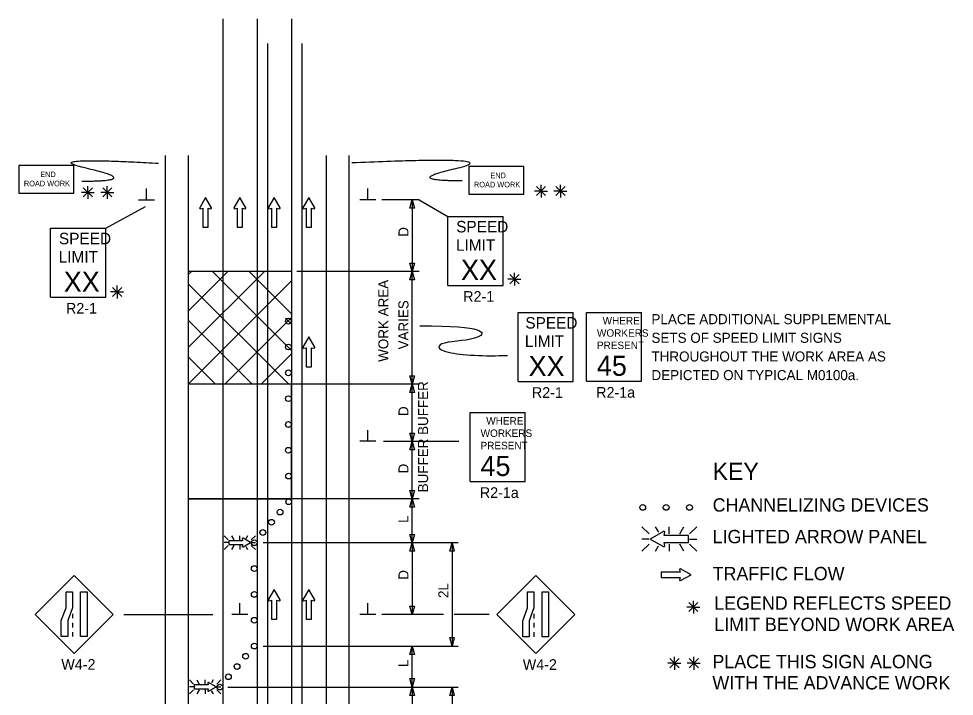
# Model space of a CAD drawing. Extents: x 16725 to 18475, y 5932 to 7023.
# Drawn here: x 16757 to 17408, y 6551 to 7023 of the extents above; entities that cross this region are included whole.
import ezdxf

# ---------------------------------------------------------------- set-up
doc = ezdxf.new("R2010")
doc.units = 0
for name, color, linetype in [('ALI_LEGAL_EX', 7, 'Continuous'), ('MT_SCRATCH_LEVEL_A', 7, 'Continuous'), ('MT_SCRATCH_LEVEL_E', 7, 'Continuous'), ('PAVT_EDGE_EX', 7, 'Continuous'), ('TRAFFIC_SIGNS_PR', 7, 'Continuous'), ('TYPICAL_TEXT_DIMEN_EX', 7, 'Continuous'), ('TYPICAL_TEXT_DIMEN_PR', 7, 'Continuous')]:
    doc.layers.add(name, color=color, linetype=linetype)

msp = doc.modelspace()

# ---------------------------------------------------------------- linework, layer by layer
at = {"layer": 'ALI_LEGAL_EX'}
for p, q in [((16898.69, 7022.86), (16898.69, 6323.13)), ((16922.69, 7022.86), (16922.69, 6323.13)), ((16946.69, 7022.86), (16946.69, 6323.13)), ((16929.88, 7005.57), (16929.88, 6176.39)), ((16953.88, 7005.57), (16953.88, 6176.39)), ((16953.88, 7005.57), (16953.88, 6176.39))]:
    msp.add_line(p, q, dxfattribs=at)
for points in [[(16898.69, 6882.86), (16898.69, 6857.86)], [(16922.69, 6882.86), (16922.69, 6857.86)], [(16946.69, 6882.86), (16946.69, 6857.86)], [(16898.69, 6782.86), (16898.69, 6757.86)], [(16922.69, 6782.86), (16922.69, 6757.86)], [(16946.69, 6782.86), (16946.69, 6757.86)], [(16898.69, 6682.86), (16898.69, 6657.86)], [(16922.69, 6682.86), (16922.69, 6657.86)], [(16898.69, 6582.86), (16898.69, 6557.86)], [(16946.69, 6582.86), (16946.69, 6557.86)]]:
    msp.add_lwpolyline(points, dxfattribs=at)
at = {"layer": 'MT_SCRATCH_LEVEL_A'}
for p, q in [((16946.69, 6846.64), (16874.69, 6846.64)), ((16874.69, 6846.64), (16874.69, 6738.67)), ((16946.69, 6846.64), (16874.69, 6846.64)), ((16874.69, 6846.64), (16874.69, 6768.1)), ((16874.69, 6844.47), (16876.86, 6846.64)), ((16874.69, 6819.01), (16902.32, 6846.64)), ((16874.69, 6793.56), (16927.77, 6846.64)), ((16946.69, 6791.56), (16891.62, 6846.64)), ((16946.69, 6817.01), (16917.07, 6846.64)), ((16874.69, 6768.1), (16946.69, 6840.1)), ((16944.7, 6768.1), (16874.69, 6838.1)), ((16919.24, 6768.1), (16874.69, 6812.65)), ((16900.15, 6768.1), (16946.69, 6814.64)), ((16946.6, 6809.85), (16942.43, 6814.01)), ((16893.79, 6768.1), (16874.69, 6787.19)), ((16925.61, 6768.1), (16946.69, 6789.19)), ((16946.69, 6768.1), (16874.69, 6768.1))]:
    msp.add_line(p, q, dxfattribs=at)
at = {"layer": 'MT_SCRATCH_LEVEL_E'}
for p, q in [((16886.79, 6898.33), (16882.68, 6891.09)), ((16890.94, 6891.09), (16886.79, 6898.33)), ((16910.69, 6898.33), (16906.58, 6891.09)), ((16914.84, 6891.09), (16910.69, 6898.33)), ((16934.6, 6898.33), (16930.49, 6891.09)), ((16938.74, 6891.09), (16934.6, 6898.33)), ((16958.65, 6898.33), (16954.54, 6891.09)), ((16962.8, 6891.09), (16958.65, 6898.33)), ((16883.16, 6890.41), (16884.94, 6890.72)), ((16884.94, 6890.72), (16884.94, 6877.46)), ((16888.68, 6877.46), (16888.68, 6890.72)), ((16888.68, 6890.72), (16890.46, 6890.41)), ((16907.06, 6890.41), (16908.84, 6890.72)), ((16908.84, 6890.72), (16908.84, 6877.46)), ((16912.58, 6877.46), (16912.58, 6890.72)), ((16912.58, 6890.72), (16914.36, 6890.41)), ((16930.97, 6890.41), (16932.74, 6890.72)), ((16932.74, 6890.72), (16932.74, 6877.46)), ((16936.49, 6877.46), (16936.49, 6890.72)), ((16936.49, 6890.72), (16938.26, 6890.41)), ((16955.02, 6890.41), (16956.8, 6890.72)), ((16956.8, 6890.72), (16956.8, 6877.46)), ((16960.54, 6877.46), (16960.54, 6890.72)), ((16960.54, 6890.72), (16962.32, 6890.41)), ((16884.94, 6877.46), (16888.68, 6877.46)), ((16908.84, 6877.46), (16912.58, 6877.46)), ((16932.74, 6877.46), (16936.49, 6877.46)), ((16956.8, 6877.46), (16960.54, 6877.46)), ((16958.65, 6801.06), (16954.54, 6793.82)), ((16962.8, 6793.82), (16958.65, 6801.06)), ((16955.02, 6793.13), (16956.8, 6793.45)), ((16956.8, 6793.45), (16956.8, 6780.19)), ((16960.54, 6780.19), (16960.54, 6793.45)), ((16960.54, 6793.45), (16962.32, 6793.13)), ((16956.8, 6780.19), (16960.54, 6780.19)), ((17217.36, 6637.12), (17204.11, 6637.12)), ((17204.11, 6637.12), (17204.11, 6633.38)), ((17217.05, 6638.9), (17217.36, 6637.12)), ((17224.97, 6635.27), (17217.73, 6639.38)), ((17204.11, 6633.38), (17217.36, 6633.38)), ((17217.36, 6633.38), (17217.05, 6631.6)), ((17217.73, 6631.12), (17224.97, 6635.27)), ((16934.6, 6625.06), (16930.49, 6617.82)), ((16938.74, 6617.82), (16934.6, 6625.06)), ((16958.65, 6625.06), (16954.54, 6617.82)), ((16962.8, 6617.82), (16958.65, 6625.06)), ((16930.97, 6617.14), (16932.74, 6617.45)), ((16932.74, 6617.45), (16932.74, 6604.19)), ((16936.49, 6604.19), (16936.49, 6617.45)), ((16936.49, 6617.45), (16938.26, 6617.14)), ((16955.02, 6617.14), (16956.8, 6617.45)), ((16956.8, 6617.45), (16956.8, 6604.19)), ((16960.54, 6604.19), (16960.54, 6617.45)), ((16960.54, 6617.45), (16962.32, 6617.14)), ((16932.74, 6604.19), (16936.49, 6604.19)), ((16956.8, 6604.19), (16960.54, 6604.19))]:
    msp.add_line(p, q, dxfattribs=at)
for centre, start, end in [((16883.09, 6890.87), 150.42484, 279.96381), ((16890.53, 6890.87), 260.03619, 29.77312), ((16906.99, 6890.87), 150.42484, 279.96381), ((16914.43, 6890.87), 260.03619, 29.77312), ((16930.89, 6890.87), 150.42484, 279.96381), ((16938.33, 6890.87), 260.03619, 29.77312), ((16954.95, 6890.87), 150.42484, 279.96381), ((16962.39, 6890.87), 260.03619, 29.77312), ((16954.95, 6793.59), 150.42484, 279.96381), ((16962.39, 6793.59), 260.03619, 29.77312), ((17217.51, 6638.97), 60.42484, 189.96381), ((17217.51, 6631.53), 170.03619, 299.77312), ((16930.89, 6617.59), 150.42484, 279.96381), ((16938.33, 6617.6), 260.03619, 29.77312), ((16954.95, 6617.59), 150.42484, 279.96381), ((16962.39, 6617.6), 260.03619, 29.77312)]:
    msp.add_arc(centre, 0.463, start, end, dxfattribs=at)
at = {"layer": 'PAVT_EDGE_EX'}
for p, q in [((16858.69, 6927.61), (16858.69, 6215.97)), ((16874.69, 6927.61), (16874.69, 6215.97)), ((16970.69, 6927.61), (16970.69, 6215.97)), ((16986.69, 6927.61), (16986.69, 6215.97))]:
    msp.add_line(p, q, dxfattribs=at)
msp.add_lwpolyline([(16946.69, 6768.1), (16874.69, 6768.1), (16874.69, 6688.1), (16946.69, 6688.1)], close=True, dxfattribs=at)
at = {"layer": 'TRAFFIC_SIGNS_PR'}
for p, q in [((17055.59, 6885.03), (17094.03, 6885.03)), ((17055.59, 6836.97), (17055.59, 6885.03)), ((17094.03, 6836.97), (17094.03, 6885.03)), ((16778.85, 6876.77), (16817.3, 6876.77)), ((16778.85, 6828.7), (16778.85, 6876.77)), ((16817.3, 6828.7), (16817.3, 6876.77)), ((17055.59, 6836.97), (17094.03, 6836.97)), ((16778.85, 6828.7), (16817.3, 6828.7)), ((17104.54, 6818), (17142.94, 6818)), ((17104.54, 6770), (17104.54, 6818)), ((17142.94, 6770), (17142.94, 6818)), ((17152.09, 6818.09), (17190.49, 6818.09)), ((17152.09, 6770.09), (17152.09, 6818.09)), ((17190.49, 6770.09), (17190.49, 6818.09)), ((17104.54, 6770), (17142.94, 6770)), ((17152.09, 6770.09), (17190.49, 6770.09)), ((17071.02, 6748.23), (17109.42, 6748.23)), ((17071.02, 6700.23), (17071.02, 6748.23)), ((17109.42, 6700.23), (17109.42, 6748.23)), ((17071.02, 6700.23), (17109.42, 6700.23)), ((17190.78, 6668.65), (17195.72, 6663.72)), ((17202.55, 6664.83), (17200.34, 6668.65)), ((17209.87, 6663.72), (17209.87, 6668.65)), ((17217.1, 6663.72), (17219.95, 6668.65)), ((17224.02, 6663.72), (17228.95, 6668.65)), ((16902.47, 6659.64), (16899.65, 6662.46)), ((16904.77, 6662.46), (16906.39, 6659.64)), ((16910.55, 6659.64), (16910.55, 6662.46)), ((16916.02, 6662.46), (16914.82, 6660.36)), ((16921.46, 6662.46), (16918.64, 6659.64)), ((16902.47, 6657.61), (16899.65, 6657.61)), ((16902.47, 6655.57), (16899.65, 6652.75)), ((16906.42, 6655.57), (16904.79, 6652.75)), ((16910.55, 6655.57), (16910.55, 6652.75)), ((16918.64, 6657.61), (16921.46, 6657.61)), ((16921.46, 6652.76), (16918.64, 6655.57)), ((17195.72, 6660.16), (17190.78, 6660.16)), ((17190.78, 6651.67), (17195.72, 6656.61)), ((17200.3, 6651.67), (17202.41, 6655.33)), ((17209.87, 6656.61), (17209.87, 6651.67)), ((17220, 6651.67), (17217.15, 6656.61)), ((17224.02, 6660.16), (17228.95, 6660.16)), ((17224.02, 6656.61), (17228.95, 6651.67)), ((16914.74, 6654.94), (16916, 6652.75)), ((16795.32, 6634.75), (16768.17, 6607.6)), ((16822.47, 6607.6), (16795.32, 6634.75)), ((17116.81, 6634.7), (17089.66, 6607.55)), ((17143.96, 6607.55), (17116.81, 6634.7)), ((16768.17, 6607.6), (16795.32, 6580.45)), ((16794.07, 6608.09), (16794.07, 6604.89)), ((16795.32, 6580.45), (16822.47, 6607.6)), ((17089.66, 6607.55), (17116.81, 6580.39)), ((17115.56, 6608.04), (17115.56, 6604.84)), ((17116.81, 6580.39), (17143.96, 6607.55)), ((16794.07, 6601.69), (16794.07, 6598.49)), ((17115.56, 6601.64), (17115.56, 6598.44)), ((16794.07, 6595.29), (16794.07, 6592.09)), ((17115.56, 6595.24), (17115.56, 6592.04)), ((16878.47, 6559.07), (16875.65, 6561.9)), ((16880.77, 6561.9), (16882.39, 6559.07)), ((16886.55, 6559.07), (16886.55, 6561.9)), ((16892.02, 6561.9), (16890.82, 6559.8)), ((16897.46, 6561.89), (16894.64, 6559.07)), ((16878.47, 6557.04), (16875.65, 6557.04)), ((16878.47, 6555.01), (16875.65, 6552.19)), ((16882.42, 6555.01), (16880.79, 6552.19)), ((16886.55, 6555.01), (16886.55, 6552.19)), ((16890.74, 6554.38), (16892, 6552.19)), ((16894.64, 6557.04), (16897.46, 6557.04)), ((16897.46, 6552.19), (16894.64, 6555.01))]:
    msp.add_line(p, q, dxfattribs=at)
for points in [[(16756.59, 6901.32), (16794.99, 6901.32), (16794.99, 6920.52), (16756.59, 6920.52)], [(17070.18, 6900.57), (17108.58, 6900.57), (17108.58, 6919.77), (17070.18, 6919.77)], [(16794.07, 6623.34), (16794.07, 6612.15), (16790.73, 6603.27), (16790.73, 6592.09), (16786.24, 6592.09), (16786.24, 6603.27), (16789.58, 6612.15), (16789.58, 6623.34)], [(16804.21, 6623.34), (16804.21, 6592.09), (16799.72, 6592.09), (16799.72, 6623.34)], [(17115.56, 6623.28), (17115.56, 6612.1), (17112.22, 6603.22), (17112.22, 6592.04), (17107.73, 6592.04), (17107.73, 6603.22), (17111.07, 6612.1), (17111.07, 6623.28)], [(17125.7, 6623.28), (17125.7, 6592.04), (17121.21, 6592.04), (17121.21, 6623.28)]]:
    msp.add_lwpolyline(points, close=True, dxfattribs=at)
for points in [[(17205.79, 6665.44), (17196.5, 6660.16), (17205.8, 6654.84)], [(17206.67, 6655.47), (17206.27, 6657.74), (17223.28, 6657.74), (17223.28, 6662.54), (17206.27, 6662.54), (17206.67, 6664.82)], [(16912.38, 6660.29), (16912.61, 6658.99), (16902.89, 6658.99), (16902.89, 6656.25), (16912.61, 6656.25), (16912.38, 6654.94)], [(16912.88, 6654.59), (16918.19, 6657.61), (16912.88, 6660.65)], [(16888.38, 6559.73), (16888.61, 6558.43), (16878.89, 6558.43), (16878.89, 6555.69), (16888.61, 6555.69), (16888.38, 6554.38)], [(16888.88, 6554.03), (16894.19, 6557.04), (16888.88, 6560.08)]]:
    msp.add_lwpolyline(points, dxfattribs=at)
for centre in [(16944.5, 6812), (16944.5, 6794), (16944.5, 6776), (16944.5, 6758), (16944.5, 6740), (16944.5, 6722), (16944.59, 6704.05), (16944.69, 6686.1), (17191.35, 6682.19), (17207.65, 6682.19), (17223.95, 6682.19), (16938.69, 6678.96), (16932.69, 6671.82), (16926.69, 6664.68), (16920.69, 6657.54), (16920.69, 6639.54), (16920.69, 6621.54), (16920.69, 6603.54), (16920.69, 6585.54), (16914.69, 6578.39), (16908.69, 6571.25), (16902.69, 6564.11), (16896.69, 6556.97)]:
    msp.add_circle(centre, 2, dxfattribs=at)
for centre, radius, start, end in [((17206.08, 6664.92), 0.598, 350.73078, 118.89165), ((16912.72, 6660.35), 0.341, 61.48329, 189.95933), ((17206.08, 6655.37), 0.597, 241.48329, 9.95933), ((16912.72, 6654.89), 0.341, 170.73078, 298.89165), ((16888.72, 6559.78), 0.341, 61.48329, 189.95933), ((16888.72, 6554.33), 0.341, 170.73078, 298.89165)]:
    msp.add_arc(centre, radius, start, end, dxfattribs=at)
for points in [[(16800.52, 6909.62), (16843.03, 6909.62), (16766.51, 6927.04), (16854.05, 6922.1)], [(17065.47, 6909.8), (17022.96, 6909.8), (17099.47, 6927.21), (16988.69, 6922.27)]]:
    msp.add_open_spline(points, degree=2, dxfattribs=at)
at = {"layer": 'TYPICAL_TEXT_DIMEN_PR'}
for p, q in [((16801.58, 6904.96), (16807.96, 6898.59)), ((16807.96, 6904.96), (16801.58, 6898.59)), ((16804.77, 6901.78), (16804.77, 6906.23)), ((16815.09, 6904.96), (16821.46, 6898.59)), ((16821.46, 6904.96), (16815.09, 6898.59)), ((16818.28, 6901.78), (16818.28, 6906.23)), ((16845.57, 6896.64), (16845.57, 6904.42)), ((16999.82, 6896.64), (16999.82, 6904.42)), ((17120.52, 6902.69), (17115.99, 6902.69)), ((17117.33, 6905.88), (17123.71, 6899.5)), ((17123.71, 6905.88), (17117.33, 6899.5)), ((17120.52, 6902.69), (17120.52, 6907.15)), ((17120.52, 6902.69), (17123.71, 6902.69)), ((17120.52, 6902.69), (17125, 6902.69)), ((17120.52, 6902.69), (17120.52, 6898.19)), ((17134.03, 6902.69), (17129.49, 6902.69)), ((17130.84, 6905.88), (17137.21, 6899.5)), ((17137.21, 6905.88), (17130.84, 6899.5)), ((17134.03, 6902.69), (17134.03, 6907.15)), ((17134.03, 6902.69), (17137.21, 6902.69)), ((17134.03, 6902.69), (17138.5, 6902.69)), ((17134.03, 6902.69), (17134.03, 6898.19)), ((16804.77, 6901.78), (16800.24, 6901.78)), ((16804.77, 6901.78), (16807.96, 6901.78)), ((16804.77, 6901.78), (16809.25, 6901.78)), ((16804.77, 6901.78), (16804.77, 6897.28)), ((16818.28, 6901.78), (16813.74, 6901.78)), ((16818.28, 6901.78), (16821.46, 6901.78)), ((16818.28, 6901.78), (16822.75, 6901.78)), ((16818.28, 6901.78), (16818.28, 6897.28)), ((16839.94, 6896.64), (16851.19, 6896.64)), ((17005.44, 6896.64), (16994.19, 6896.64)), ((17035.69, 6896.64), (17009.69, 6896.64)), ((17029.12, 6890.77), (17030.69, 6896.64)), ((17030.69, 6896.64), (17030.69, 6846.64)), ((17030.69, 6896.64), (17032.26, 6890.77)), ((17035.69, 6896.64), (17055.59, 6885.03)), ((16817.25, 6876.77), (16844.96, 6892.05)), ((17030.69, 6890.77), (17029.12, 6890.77)), ((17032.26, 6890.77), (17030.69, 6890.77)), ((17030.69, 6846.64), (17029.12, 6852.5)), ((17029.12, 6852.5), (17030.69, 6852.5)), ((17030.69, 6852.5), (17032.26, 6852.5)), ((17032.26, 6852.5), (17030.69, 6846.64)), ((17035.69, 6846.64), (16950.31, 6846.64)), ((17029.12, 6840.77), (17030.69, 6846.64)), ((17030.69, 6768.1), (17030.69, 6846.64)), ((17030.69, 6846.64), (17032.26, 6840.77)), ((17098.79, 6844.52), (17105.16, 6838.14)), ((17105.16, 6844.52), (17098.79, 6838.14)), ((17101.97, 6841.33), (17101.97, 6845.79)), ((17030.69, 6840.77), (17029.12, 6840.77)), ((17032.26, 6840.77), (17030.69, 6840.77)), ((17101.97, 6841.33), (17097.44, 6841.33)), ((17101.97, 6841.33), (17105.16, 6841.33)), ((17101.97, 6841.33), (17106.45, 6841.33)), ((17101.97, 6841.33), (17101.97, 6836.83)), ((16825.14, 6832.39), (16820.6, 6832.39)), ((16821.95, 6835.57), (16828.32, 6829.2)), ((16828.32, 6835.57), (16821.95, 6829.2)), ((16825.14, 6832.39), (16825.14, 6836.84)), ((16825.14, 6832.39), (16828.32, 6832.39)), ((16825.14, 6832.39), (16829.61, 6832.39)), ((16825.14, 6832.39), (16825.14, 6827.89)), ((17030.69, 6768.1), (17029.12, 6773.96)), ((17029.12, 6773.96), (17030.69, 6773.96)), ((17030.69, 6773.96), (17032.26, 6773.96)), ((17032.26, 6773.96), (17030.69, 6768.1)), ((17035.69, 6768.1), (16946.69, 6768.1)), ((17029.12, 6762.24), (17030.69, 6768.1)), ((17030.69, 6728.1), (17030.69, 6768.1)), ((17030.69, 6768.1), (17032.26, 6762.24)), ((17030.69, 6762.24), (17029.12, 6762.24)), ((17032.26, 6762.24), (17030.69, 6762.24)), ((16999.82, 6728.36), (16999.82, 6736.14)), ((17030.69, 6728.1), (17029.12, 6733.96)), ((17029.12, 6733.96), (17030.69, 6733.96)), ((17030.69, 6733.96), (17032.26, 6733.96)), ((17032.26, 6733.96), (17030.69, 6728.1)), ((17005.44, 6728.36), (16994.19, 6728.36)), ((17063.31, 6728.1), (17010.84, 6728.1)), ((17029.12, 6722.24), (17030.69, 6728.1)), ((17030.69, 6688.1), (17030.69, 6728.1)), ((17030.69, 6728.1), (17032.26, 6722.24)), ((17030.69, 6722.24), (17029.12, 6722.24)), ((17032.26, 6722.24), (17030.69, 6722.24)), ((17035.69, 6688.1), (16874.69, 6688.1)), ((17030.69, 6688.1), (17029.12, 6693.96)), ((17029.12, 6693.96), (17030.69, 6693.96)), ((17029.12, 6682.24), (17030.69, 6688.1)), ((17030.69, 6693.96), (17032.26, 6693.96)), ((17032.26, 6693.96), (17030.69, 6688.1)), ((17030.69, 6657.53), (17030.69, 6688.1)), ((17030.69, 6688.1), (17032.26, 6682.24)), ((17030.69, 6682.24), (17029.12, 6682.24)), ((17032.26, 6682.24), (17030.69, 6682.24)), ((17030.69, 6657.53), (17029.12, 6663.4)), ((17029.12, 6663.4), (17030.69, 6663.4)), ((17030.69, 6663.4), (17032.26, 6663.4)), ((17032.26, 6663.4), (17030.69, 6657.53)), ((17062.74, 6657.53), (16926.92, 6657.53)), ((17029.12, 6651.67), (17030.69, 6657.53)), ((17030.69, 6657.53), (17030.69, 6607.53)), ((17030.69, 6657.53), (17032.26, 6651.67)), ((17056.93, 6651.67), (17058.5, 6657.53)), ((17058.5, 6657.53), (17060.07, 6651.67)), ((17058.5, 6657.53), (17058.5, 6585.53)), ((17030.69, 6651.67), (17029.12, 6651.67)), ((17032.26, 6651.67), (17030.69, 6651.67)), ((17058.5, 6651.67), (17056.93, 6651.67)), ((17060.07, 6651.67), (17058.5, 6651.67)), ((17229.84, 6615.89), (17223.46, 6609.51)), ((17223.47, 6615.89), (17229.84, 6609.51)), ((17226.65, 6612.7), (17226.65, 6617.16)), ((16910.64, 6607.53), (16910.64, 6615.32)), ((16999.82, 6607.53), (16999.82, 6615.32)), ((17030.69, 6607.53), (17029.12, 6613.4)), ((17029.12, 6613.4), (17030.69, 6613.4)), ((17030.69, 6613.4), (17032.26, 6613.4)), ((17032.26, 6613.4), (17030.69, 6607.53)), ((17226.65, 6612.7), (17222.12, 6612.7)), ((17226.65, 6612.7), (17229.84, 6612.7)), ((17226.65, 6612.7), (17231.13, 6612.7)), ((17226.65, 6612.7), (17226.65, 6608.2)), ((16829.94, 6607.53), (16891.95, 6607.53)), ((16916.26, 6607.53), (16905.01, 6607.53)), ((17005.44, 6607.53), (16994.19, 6607.53)), ((17052.49, 6607.53), (17009.69, 6607.53)), ((17084.27, 6607.53), (17060.06, 6607.53)), ((17058.5, 6585.53), (17056.93, 6591.4)), ((17056.93, 6591.4), (17058.5, 6591.4)), ((17058.5, 6591.4), (17060.07, 6591.4)), ((17060.07, 6591.4), (17058.5, 6585.53)), ((16926.92, 6585.53), (17062.74, 6585.53)), ((17029.12, 6579.67), (17030.69, 6585.53)), ((17030.69, 6556.97), (17030.69, 6585.53)), ((17030.69, 6585.53), (17032.26, 6579.67)), ((17030.69, 6579.67), (17029.12, 6579.67)), ((17032.26, 6579.67), (17030.69, 6579.67)), ((17210.24, 6576.76), (17216.62, 6570.38)), ((17216.62, 6576.76), (17210.24, 6570.38)), ((17213.43, 6573.57), (17213.43, 6578.03)), ((17223.75, 6576.76), (17230.12, 6570.38)), ((17230.12, 6576.76), (17223.75, 6570.38)), ((17226.94, 6573.57), (17226.94, 6578.03)), ((17213.43, 6573.57), (17208.9, 6573.57)), ((17213.43, 6573.57), (17216.62, 6573.57)), ((17213.43, 6573.57), (17217.91, 6573.57)), ((17213.43, 6573.57), (17213.43, 6569.07)), ((17226.94, 6573.57), (17222.4, 6573.57)), ((17226.94, 6573.57), (17230.12, 6573.57)), ((17226.94, 6573.57), (17231.41, 6573.57)), ((17226.94, 6573.57), (17226.94, 6569.07)), ((17030.69, 6556.97), (17029.12, 6562.84)), ((17029.12, 6562.84), (17030.69, 6562.84)), ((17030.69, 6562.84), (17032.26, 6562.84)), ((17032.26, 6562.84), (17030.69, 6556.97)), ((16902.24, 6556.97), (17062.74, 6556.97)), ((17029.12, 6551.11), (17030.69, 6556.97)), ((17030.69, 6551.11), (17029.12, 6551.11)), ((17030.69, 6556.97), (17030.69, 6506.97)), ((17030.69, 6556.97), (17032.26, 6551.11)), ((17032.26, 6551.11), (17030.69, 6551.11)), ((17056.93, 6551.11), (17058.5, 6556.97)), ((17058.5, 6551.11), (17056.93, 6551.11)), ((17058.5, 6556.97), (17060.07, 6551.11)), ((17058.5, 6556.97), (17058.5, 6484.97)), ((17060.07, 6551.11), (17058.5, 6551.11))]:
    msp.add_line(p, q, dxfattribs=at)
for points, degree in [([(17036, 6808.71), (17082.47, 6809.04), (17082.47, 6798.29), (17047.55, 6798.29), (17047.55, 6789.24), (17081.76, 6787.48), (17097.23, 6788.15)], 3), ([(17319.6, 6613.29), (17319.62, 6613.29), (17319.63, 6613.29), (17319.63, 6613.29)], 2)]:
    msp.add_open_spline(points, degree=degree, dxfattribs=at)

# ---------------------------------------------------------------- texts
at = {"layer": 'TRAFFIC_SIGNS_PR'}
for s, height, p in [('END', 3.831, (16771.59, 6912.45)), ('ROAD WORK', 3.831, (16760.2, 6906.06)), ('ROAD WORK', 3.831, (17073.79, 6905.31)), ('END', 3.831, (17085.18, 6911.69)), ('SPEED', 8.01, (17061.36, 6873.88)), ('SPEED', 8.01, (16784.63, 6865.61)), ('LIMIT', 8.01, (17061.2, 6861.06)), ('LIMIT', 8.01, (16784.47, 6852.8)), ('XX', 14.048, (17064.71, 6840.73)), ('XX', 14.048, (16787.98, 6832.47)), ('R2-1', 7.449, (17066.28, 6825.52)), ('R2-1', 7.449, (16789.54, 6817.25)), ('SPEED', 8, (17109.57, 6806.86)), ('WHERE', 5.2, (17163.4, 6809.77)), ('PLACE ADDITIONAL SUPPLEMENTAL', 7, (17197.43, 6809.91)), ('WORKERS', 5.2, (17159.47, 6801.17)), ('LIMIT', 8, (17109.24, 6794.06)), ('SETS OF SPEED LIMIT SIGNS', 7, (17197.43, 6796.91)), ('PRESENT', 5.2, (17159.41, 6792.57)), ('XX', 14.031, (17111.84, 6773.76)), ('45', 14.031, (17159.4, 6773.94)), ('THROUGHOUT THE WORK AREA AS', 7, (17197.43, 6783.91)), ('DEPICTED ON TYPICAL M0100a.', 7, (17197.43, 6770.91)), ('R2-1', 7.44, (17114.14, 6758.56)), ('R2-1a', 7.44, (17158.94, 6758.65)), ('WHERE', 5.2, (17082.33, 6739.91)), ('WORKERS', 5.2, (17078.4, 6731.31)), ('PRESENT', 5.2, (17078.33, 6722.71)), ('45', 14.031, (17078.32, 6704.08)), ('R2-1a', 7.44, (17077.87, 6688.79)), ('W4-2', 7.44, (16786.28, 6569.01)), ('W4-2', 7.44, (17107.77, 6568.95))]:
    msp.add_text(s, height=height, dxfattribs=at).set_placement(p)
at = {"layer": 'TYPICAL_TEXT_DIMEN_EX'}
for s, height, p in [('KEY', 12, (17240.04, 6701.29)), ('CHANNELIZING DEVICES', 9.3, (17240.04, 6679.24)), ('LIGHTED ARROW PANEL', 9.3, (17240.04, 6657.19)), ('TRAFFIC FLOW', 9.3, (17240.04, 6631.39)), ('LEGEND REFLECTS SPEED', 9.3, (17241.2, 6610.8)), ('LIMIT BEYOND WORK AREA', 9.3, (17241.2, 6596)), ('PLACE THIS SIGN ALONG', 9.3, (17239.88, 6570.07)), ('WITH THE ADVANCE WORK', 9.3, (17239.88, 6555.27))]:
    msp.add_text(s, height=height, dxfattribs=at).set_placement(p)
at = {"layer": 'TYPICAL_TEXT_DIMEN_PR'}
for s, p in [('D', (17028.14, 6870.85)), ('WORK AREA', (17014.14, 6783.65)), ('VARIES', (17028.14, 6792.29)), ('BUFFER', (17041.82, 6732.72)), ('D', (17028.14, 6745.87)), ('BUFFER', (17041.82, 6692.72)), ('D', (17028.14, 6705.87)), ('L', (17028.14, 6671.39)), ('D', (17028.14, 6631.75)), ('2L', (17055.94, 6619.04)), ('L', (17028.14, 6570.83))]:
    msp.add_text(s, height=7, rotation=90, dxfattribs=at).set_placement(p)

doc.saveas('drawing.dxf')
